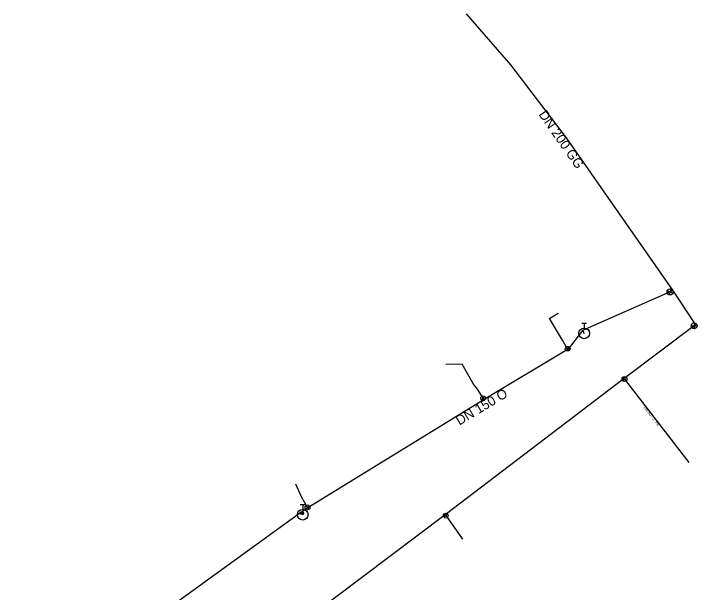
# Model space of a CAD drawing. Extents: x -451555 to -451079, y -1102113 to -1101586.
# Drawn here: x -451400.3 to -451286.4, y -1101682.1 to -1101585.8 of the extents above; entities that cross this region are included whole.
import ezdxf

# ---------------------------------------------------------------- set-up
doc = ezdxf.new("R2010")
doc.units = 0
for name, color, linetype in [('_hydrantova_odbocka_', 7, 'Continuous'), ('_pripojka_prevzato_z_dokumentace_', 7, 'Continuous'), ('_voda_smvak_prevzato_z_dokumentace_', 7, 'Continuous'), ('Default', 7, 'Continuous'), ('MoLevel 27', 7, 'Continuous'), ('MoLevel 28', 7, 'Continuous'), ('MoLevel 46', 7, 'Continuous'), ('MoLevel 53', 7, 'Continuous'), ('MoLevel 55', 7, 'Continuous')]:
    doc.layers.add(name, color=color, linetype=linetype)

# ---------------------------------------------------------------- blocks, each defined once
blk = doc.blocks.new('_uzaver_')
at = {"layer": 'Default'}
for p, q in [((-0.000035, -0.000035), (0.000035, 0.000035)), ((0.000035, -0.000035), (-0.000035, 0.000035))]:
    blk.add_line(p, q, dxfattribs=at)
for radius in [0.00005, 0.0000025]:
    blk.add_circle((0, 0), radius, dxfattribs=at)
blk = doc.blocks.new('_uzaver_pripojka_')
at = {"layer": 'Default'}
for p, q in [((-0.000035, -0.000035), (0.000035, 0.000035)), ((0.000035, -0.000035), (-0.000035, 0.000035))]:
    blk.add_line(p, q, dxfattribs=at)
for radius in [0.00005, 0.0000025]:
    blk.add_circle((0, 0), radius, dxfattribs=at)
blk = doc.blocks.new('_hydrant_voda_')
at = {"layer": 'Default'}
for p, q in [((-0.0000225, 0.000095), (0.0000225, 0.000095)), ((0, 0.000095), (0, 0.00005))]:
    blk.add_line(p, q, dxfattribs=at)
blk.add_circle((0, 0), 0.00005, dxfattribs=at)

msp = doc.modelspace()

# ---------------------------------------------------------------- linework, layer by layer
at = {"layer": '_hydrantova_odbocka_'}
msp.add_line((-451305.65, -1101638.53), (-451305.36, -1101639.01), dxfattribs=at)
msp.add_lwpolyline([(-451352.37, -1101668.69), (-451352.31, -1101668.89), (-451352.21, -1101669.17)], dxfattribs=at)
at = {"layer": '_pripojka_prevzato_z_dokumentace_'}
msp.add_line((-451352.4, -1101666.19), (-451353.36, -1101664.07), dxfattribs=at)
for points in [[(-451308.99, -1101640.14), (-451311.13, -1101636.54), (-451309.69, -1101635.65)], [(-451308.03, -1101641.66), (-451308.12, -1101641.57), (-451308.99, -1101640.14)], [(-451323.13, -1101648.3), (-451323.77, -1101647.44), (-451325.66, -1101644.12), (-451328.39, -1101644.2)], [(-451298.73, -1101646.49), (-451298.65, -1101646.6), (-451287.93, -1101660.46)], [(-451322, -1101650.02), (-451322.17, -1101649.8), (-451323.13, -1101648.3)], [(-451351.38, -1101668.04), (-451351.42, -1101667.95), (-451352.4, -1101666.19)], [(-451328.51, -1101669.18), (-451328.4, -1101669.32), (-451325.59, -1101673.26)]]:
    msp.add_lwpolyline(points, dxfattribs=at)
at = {"layer": '_voda_smvak_prevzato_z_dokumentace_'}
for p, q in [((-451290.65, -1101631.84), (-451291.07, -1101632.11)), ((-451290.65, -1101631.84), (-451286.82, -1101637.6)), ((-451286.82, -1101637.6), (-451287.07, -1101637.76))]:
    msp.add_line(p, q, dxfattribs=at)
for points in [[(-451325.01, -1101585.83), (-451317.61, -1101594.32), (-451308.34, -1101606.49), (-451290.65, -1101631.84)], [(-451291.07, -1101632.11), (-451305.65, -1101638.53), (-451308.03, -1101641.66), (-451322, -1101650.02), (-451351.38, -1101668.04), (-451352.37, -1101668.69)], [(-451287.07, -1101637.76), (-451298.73, -1101646.49), (-451328.51, -1101669.18), (-451365.13, -1101696.77), (-451388.63, -1101713.82), (-451391.04, -1101715.88)], [(-451352.37, -1101668.69), (-451374.89, -1101685.01), (-451391.64, -1101696.06), (-451420.33, -1101714.98), (-451434, -1101726.73), (-451445.03, -1101735.74), (-451449.89, -1101750.62)]]:
    msp.add_lwpolyline(points, dxfattribs=at)

# ---------------------------------------------------------------- block references
at = {"layer": 'MoLevel 27', "xscale": 10000}
for p, yscale, rotation in [((-451291.07, -1101632.11), 10000, -156.25172068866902), ((-451287.07, -1101637.76), 10000.000000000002, -143.177557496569)]:
    msp.add_blockref('_uzaver_', p, dxfattribs=dict(at, yscale=yscale, rotation=rotation))
at = {"layer": 'MoLevel 27', "xscale": 5000, "yscale": 5000}
msp.add_blockref('_uzaver_', (-451352.31, -1101668.89), dxfattribs=at)
at = {"layer": 'MoLevel 28', "xscale": 17636.68430335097, "yscale": 17636.68430335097}
for p in [(-451305.36, -1101639.01), (-451352.21, -1101669.17)]:
    msp.add_blockref('_hydrant_voda_', p, dxfattribs=at)
at = {"layer": 'MoLevel 53', "xscale": 7999.999999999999, "yscale": 7999.999999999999}
for p in [(-451308.12, -1101641.57), (-451298.65, -1101646.6), (-451322.17, -1101649.8), (-451351.42, -1101667.95), (-451328.4, -1101669.32)]:
    msp.add_blockref('_uzaver_pripojka_', p, dxfattribs=at)

# ---------------------------------------------------------------- texts
at = {"layer": 'MoLevel 46'}
for s, rotation, p in [('DN 200 GG', 304.9085, (-451313.01, -1101602.6)), ('DN 150 O', 30.8835, (-451326.13, -1101654.36))]:
    msp.add_text(s, height=1.605, rotation=rotation, dxfattribs=at).set_placement(p)
at = {"layer": 'MoLevel 55'}
msp.add_text("DN 50 - 2'' PE", height=0.455, rotation=307.7135, dxfattribs=at).set_placement((-451295.52, -1101651.38))

doc.saveas('drawing.dxf')
